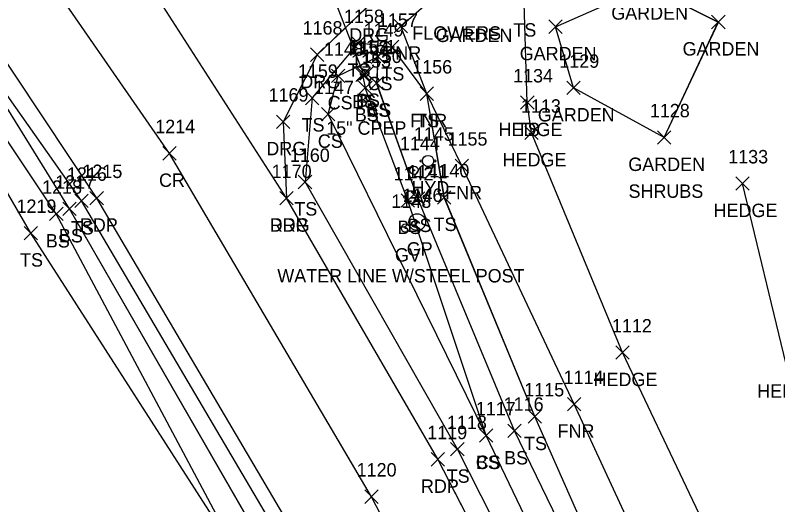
# Model space of a CAD drawing. Extents: x 1415642 to 1422021, y 544543 to 547232.
# Drawn here: x 1416447 to 1416560.6, y 546411.7 to 546484.6 of the extents above; entities that cross this region are included whole.
import ezdxf

# ---------------------------------------------------------------- set-up
doc = ezdxf.new("R2010")
doc.units = 0
for name, color, linetype in [('D_A', 7, 'Continuous'), ('D_C', 7, 'Continuous'), ('D_I', 7, 'Continuous'), ('D_TIC', 7, 'Continuous'), ('DCP', 7, 'Continuous'), ('L_A', 7, 'Continuous'), ('L_C', 7, 'Continuous'), ('L_I', 7, 'Continuous'), ('L_TIC', 7, 'Continuous'), ('LAHR', 7, 'Continuous'), ('LAPB', 7, 'Continuous'), ('LELB', 7, 'Continuous'), ('LFNC', 7, 'Continuous'), ('P_A', 7, 'Continuous'), ('P_I', 7, 'Continuous'), ('P_TIC', 7, 'Continuous'), ('PET', 7, 'Continuous'), ('PRC', 7, 'Continuous'), ('R_A', 7, 'Continuous'), ('R_C', 7, 'Continuous'), ('R_I', 7, 'Continuous'), ('R_TIC', 7, 'Continuous'), ('RDG', 7, 'Continuous'), ('RGP', 7, 'Continuous'), ('U_A', 7, 'Continuous'), ('U_I', 7, 'Continuous'), ('UWFH', 7, 'Continuous'), ('UWV', 7, 'Continuous')]:
    doc.layers.add(name, color=color, linetype=linetype)

msp = doc.modelspace()

# ---------------------------------------------------------------- linework, layer by layer
at = {"layer": 'D_TIC'}
for points in [[(1416497.95, 546474.82), (1416499.95, 546476.82)], [(1416499.95, 546474.82), (1416497.95, 546476.82)]]:
    msp.add_lwpolyline(points, dxfattribs=at)
at = {"layer": 'DCP'}
msp.add_lwpolyline([(1416498.95, 546475.82), (1416487.7, 546504.64)], dxfattribs=at)
msp.add_lwpolyline([(1416498.95, 546475.82), (1416487.7, 546504.64)], dxfattribs=at)
at = {"layer": 'L_TIC'}
for points in [[(1416503.48, 546482), (1416505.48, 546484)], [(1416505.48, 546482), (1416503.48, 546484)], [(1416526.52, 546481.92), (1416528.52, 546483.92)], [(1416528.52, 546481.92), (1416526.52, 546483.92)], [(1416550.79, 546482.62), (1416552.79, 546484.62)], [(1416552.79, 546482.62), (1416550.79, 546484.62)], [(1416550.79, 546482.62), (1416552.79, 546484.62)], [(1416552.79, 546482.62), (1416550.79, 546484.62)], [(1416497.12, 546479.46), (1416499.12, 546481.46)], [(1416499.12, 546479.46), (1416497.12, 546481.46)], [(1416502.17, 546478.89), (1416504.17, 546480.89)], [(1416504.17, 546478.89), (1416502.17, 546480.89)], [(1416500.06, 546477.45), (1416502.06, 546479.45)], [(1416502.06, 546477.45), (1416500.06, 546479.45)], [(1416498.33, 546474.96), (1416500.33, 546476.96)], [(1416500.33, 546474.96), (1416498.33, 546476.96)], [(1416494.12, 546474.6), (1416496.12, 546476.6)], [(1416496.12, 546474.6), (1416494.12, 546476.6)], [(1416497.77, 546474.76), (1416499.77, 546476.76)], [(1416499.77, 546474.76), (1416497.77, 546476.76)], [(1416498.17, 546472.82), (1416500.17, 546474.82)], [(1416500.17, 546472.82), (1416498.17, 546474.82)], [(1416498.17, 546472.82), (1416500.17, 546474.82)], [(1416500.17, 546472.82), (1416498.17, 546474.82)], [(1416499.86, 546473.51), (1416501.86, 546475.51)], [(1416501.86, 546473.51), (1416499.86, 546475.51)], [(1416499.86, 546473.51), (1416501.86, 546475.51)], [(1416501.86, 546473.51), (1416499.86, 546475.51)], [(1416529.22, 546472.8), (1416531.22, 546474.8)], [(1416531.22, 546472.8), (1416529.22, 546474.8)], [(1416507.34, 546471.94), (1416509.34, 546473.94)], [(1416509.34, 546471.94), (1416507.34, 546473.94)], [(1416507.34, 546471.94), (1416509.34, 546473.94)], [(1416509.34, 546471.94), (1416507.34, 546473.94)], [(1416490.26, 546471.3), (1416492.26, 546473.3)], [(1416492.26, 546471.3), (1416490.26, 546473.3)], [(1416522.32, 546470.61), (1416524.32, 546472.61)], [(1416524.32, 546470.61), (1416522.32, 546472.61)], [(1416522.32, 546470.61), (1416524.32, 546472.61)], [(1416524.32, 546470.61), (1416522.32, 546472.61)], [(1416492.65, 546468.87), (1416494.65, 546470.87)], [(1416494.65, 546468.87), (1416492.65, 546470.87)], [(1416522.93, 546466.1), (1416524.93, 546468.1)], [(1416524.93, 546466.1), (1416522.93, 546468.1)], [(1416542.7, 546465.42), (1416544.7, 546467.42)], [(1416544.7, 546465.42), (1416542.7, 546467.42)], [(1416542.7, 546465.42), (1416544.7, 546467.42)], [(1416544.7, 546465.42), (1416542.7, 546467.42)], [(1416512.55, 546461.2), (1416514.55, 546463.2)], [(1416514.55, 546461.2), (1416512.55, 546463.2)], [(1416489.18, 546458.78), (1416491.18, 546460.78)], [(1416491.18, 546458.78), (1416489.18, 546460.78)], [(1416489.18, 546458.78), (1416491.18, 546460.78)], [(1416491.18, 546458.78), (1416489.18, 546460.78)], [(1416554.38, 546458.55), (1416556.38, 546460.55)], [(1416556.38, 546458.55), (1416554.38, 546460.55)], [(1416455.87, 546455.96), (1416457.87, 546457.96)], [(1416457.87, 546455.96), (1416455.87, 546457.96)], [(1416504.52, 546456.03), (1416506.52, 546458.03)], [(1416506.52, 546456.03), (1416504.52, 546458.03)], [(1416506.02, 546456.32), (1416508.02, 546458.32)], [(1416508.02, 546456.32), (1416506.02, 546458.32)], [(1416509.94, 546456.47), (1416511.94, 546458.47)], [(1416511.94, 546456.47), (1416509.94, 546458.47)], [(1416454.06, 546454.78), (1416456.06, 546456.78)], [(1416456.06, 546454.78), (1416454.06, 546456.78)], [(1416452.11, 546454.02), (1416454.11, 546456.02)], [(1416454.11, 546454.02), (1416452.11, 546456.02)], [(1416448.3, 546451.17), (1416450.3, 546453.17)], [(1416450.3, 546451.17), (1416448.3, 546453.17)], [(1416536.49, 546433.36), (1416538.49, 546435.36)], [(1416538.49, 546433.36), (1416536.49, 546435.36)], [(1416529.29, 546425.68), (1416531.29, 546427.68)], [(1416531.29, 546425.68), (1416529.29, 546427.68)], [(1416523.42, 546423.83), (1416525.42, 546425.83)], [(1416525.42, 546423.83), (1416523.42, 546425.83)], [(1416520.41, 546421.69), (1416522.41, 546423.69)], [(1416522.41, 546421.69), (1416520.41, 546423.69)], [(1416516.2, 546421.01), (1416518.2, 546423.01)], [(1416518.2, 546421.01), (1416516.2, 546423.01)], [(1416516.2, 546421.01), (1416518.2, 546423.01)], [(1416518.2, 546421.01), (1416516.2, 546423.01)], [(1416511.89, 546418.96), (1416513.89, 546420.96)], [(1416513.89, 546418.96), (1416511.89, 546420.96)]]:
    msp.add_lwpolyline(points, dxfattribs=at)
at = {"layer": 'LAHR'}
for points in [[(1416601.24, 546292.69), (1416586.35, 546326.71), (1416573.12, 546362.04), (1416558.49, 546390.29), (1416537.49, 546434.36), (1416523.93, 546467.1), (1416523.32, 546471.61)], [(1416601.24, 546292.69), (1416586.35, 546326.71), (1416573.12, 546362.03), (1416558.49, 546390.29), (1416537.49, 546434.36), (1416523.93, 546467.1), (1416523.32, 546471.61)], [(1416579.62, 546377.83), (1416571.96, 546396.11), (1416561.88, 546432.63), (1416555.38, 546459.56)], [(1416579.62, 546377.83), (1416571.96, 546396.12), (1416561.88, 546432.63), (1416555.38, 546459.55)]]:
    msp.add_lwpolyline(points, dxfattribs=at)
at = {"layer": 'LAPB'}
for points in [[(1416543.7, 546466.42), (1416530.22, 546473.8), (1416527.52, 546482.92), (1416541.16, 546488.97), (1416551.79, 546483.62)], [(1416543.71, 546466.42), (1416530.22, 546473.8), (1416527.52, 546482.91), (1416541.17, 546488.97), (1416551.8, 546483.62)], [(1416543.7, 546466.42), (1416551.79, 546483.62)], [(1416543.71, 546466.42), (1416551.8, 546483.62)]]:
    msp.add_lwpolyline(points, dxfattribs=at)
at = {"layer": 'LELB'}
for points in [[(1416578, 546177.77), (1416578.55, 546199.27), (1416573.9, 546214.14), (1416552.43, 546269), (1416536.22, 546304.5), (1416520.22, 546335.71), (1416500.65, 546371.21), (1416484.25, 546405.14), (1416455.06, 546455.78), (1416435.93, 546486.65), (1416412.14, 546519.01), (1416383.64, 546557.13), (1416352.74, 546592.54), (1416331.82, 546618.14), (1416293.94, 546655.61), (1416274.22, 546680.91), (1416245.72, 546708.98), (1416224.27, 546729.93), (1416198.14, 546753.3), (1416170.94, 546765.48), (1416158.5, 546767.31), (1416141.08, 546772.75), (1416136.01, 546776.95), (1416129, 546780.64)], [(1416578, 546177.77), (1416578.55, 546199.27), (1416573.9, 546214.14), (1416552.42, 546269.01), (1416536.22, 546304.5), (1416520.22, 546335.71), (1416500.65, 546371.22), (1416484.25, 546405.15), (1416455.06, 546455.79), (1416435.93, 546486.65), (1416412.14, 546519.01), (1416383.65, 546557.13), (1416352.74, 546592.54), (1416331.82, 546618.14), (1416293.94, 546655.62), (1416274.22, 546680.91), (1416245.72, 546708.98), (1416224.27, 546729.93), (1416198.14, 546753.3), (1416170.94, 546765.48), (1416158.51, 546767.31), (1416141.09, 546772.75), (1416136.01, 546776.96), (1416129.01, 546780.64)], [(1416503.76, 546247.98), (1416498.74, 546274.69), (1416501.23, 546308.66), (1416502.98, 546324.04), (1416489.47, 546365.32), (1416480.57, 546403.46), (1416453.11, 546455.02), (1416433.2, 546484.78), (1416409.26, 546516.78), (1416378.25, 546552.92), (1416343.61, 546583.91), (1416327.57, 546614.09), (1416289.4, 546651.59), (1416267.58, 546675.69), (1416237.14, 546697.31), (1416220.66, 546725.9), (1416195.41, 546750.9), (1416170.78, 546763.33), (1416158.82, 546764.49), (1416140.16, 546770.72), (1416135.4, 546775.05), (1416128.27, 546778.63)], [(1416503.76, 546247.98), (1416498.74, 546274.69), (1416501.24, 546308.65), (1416502.98, 546324.03), (1416489.47, 546365.32), (1416480.57, 546403.46), (1416453.11, 546455.02), (1416433.2, 546484.78), (1416409.26, 546516.79), (1416378.25, 546552.92), (1416343.61, 546583.91), (1416327.58, 546614.09), (1416289.4, 546651.59), (1416267.58, 546675.69), (1416237.14, 546697.31), (1416220.66, 546725.9), (1416195.42, 546750.9), (1416170.78, 546763.33), (1416158.81, 546764.5), (1416140.16, 546770.72), (1416135.4, 546775.05), (1416128.28, 546778.62)], [(1416480.57, 546403.46), (1416449.3, 546452.17), (1416431.01, 546483.64), (1416405.55, 546512.84), (1416372.51, 546548.53), (1416341.49, 546581.99), (1416324.84, 546612.16), (1416286, 546648.13), (1416263.12, 546671.71)], [(1416480.57, 546403.46), (1416449.3, 546452.17), (1416431.01, 546483.64), (1416405.56, 546512.84), (1416372.51, 546548.53), (1416341.49, 546581.99), (1416324.84, 546612.16), (1416286, 546648.13), (1416263.12, 546671.71)], [(1416587.9, 546190.79), (1416583.62, 546199.97), (1416577.46, 546215.02), (1416552.43, 546269), (1416533.39, 546301.47), (1416525.26, 546316.84), (1416520.22, 546335.71), (1416504.13, 546372.91), (1416486.87, 546406.07), (1416456.87, 546456.96), (1416435.93, 546486.65), (1416413.88, 546519.84), (1416385.73, 546558.12)], [(1416587.91, 546190.79), (1416583.61, 546199.97), (1416577.46, 546215.02), (1416552.42, 546269.01), (1416533.39, 546301.47), (1416525.26, 546316.84), (1416520.22, 546335.71), (1416504.13, 546372.91), (1416486.87, 546406.07), (1416456.87, 546456.96), (1416435.93, 546486.65), (1416413.88, 546519.84), (1416385.73, 546558.12)], [(1416523.32, 546471.61), (1416522.83, 546486.44), (1416538.17, 546498.28)], [(1416523.32, 546471.61), (1416522.83, 546486.44), (1416538.17, 546498.28)], [(1416547.3, 546389.95), (1416538.28, 546393.51), (1416524.42, 546424.83), (1416510.94, 546457.47), (1416508.34, 546472.94), (1416503.17, 546479.89), (1416498.12, 546480.46), (1416491.26, 546472.3), (1416490.18, 546459.78)], [(1416547.3, 546389.95), (1416538.28, 546393.51), (1416524.42, 546424.83), (1416510.95, 546457.47), (1416508.35, 546472.93), (1416503.17, 546479.89), (1416498.12, 546480.46), (1416491.25, 546472.3), (1416490.18, 546459.78)], [(1416517.2, 546422.01), (1416493.65, 546469.87), (1416495.12, 546475.6), (1416501.06, 546478.45), (1416500.86, 546474.51)], [(1416517.2, 546422.02), (1416493.65, 546469.87), (1416495.12, 546475.6), (1416501.06, 546478.45), (1416500.87, 546474.51)], [(1416624.83, 546188.33), (1416609.68, 546228.85), (1416587.46, 546280.33), (1416569.58, 546317.95), (1416555.08, 546351.62), (1416539.63, 546384.17), (1416546.45, 546386.59), (1416544.38, 546389.65), (1416537.72, 546389.11), (1416521.41, 546422.69), (1416507.02, 546457.32), (1416500.86, 546474.51), (1416499.33, 546475.96), (1416498.77, 546475.76), (1416499.17, 546473.82)], [(1416624.83, 546188.34), (1416609.68, 546228.85), (1416587.45, 546280.34), (1416569.58, 546317.95), (1416555.08, 546351.63), (1416539.63, 546384.17), (1416546.45, 546386.59), (1416544.38, 546389.64), (1416537.72, 546389.12), (1416521.42, 546422.68), (1416507.02, 546457.32), (1416500.87, 546474.51), (1416499.33, 546475.96), (1416498.77, 546475.76), (1416499.17, 546473.83)], [(1416624.13, 546188.48), (1416606.9, 546227.58), (1416585.22, 546279.32), (1416567.76, 546317.19), (1416553.66, 546350.45), (1416534.43, 546386.06), (1416517.2, 546422.02), (1416505.52, 546457.03), (1416499.17, 546473.83)], [(1416624.13, 546188.48), (1416606.9, 546227.58), (1416585.22, 546279.32), (1416567.76, 546317.19), (1416553.66, 546350.45), (1416534.43, 546386.06), (1416517.2, 546422.01), (1416505.52, 546457.03), (1416499.17, 546473.82)], [(1416620.93, 546187.09), (1416604.47, 546226.81), (1416580.95, 546278.02), (1416564.18, 546315.62), (1416549.05, 546348.52), (1416530.53, 546385.22), (1416512.89, 546419.96), (1416490.18, 546459.78)], [(1416620.93, 546187.09), (1416604.48, 546226.8), (1416580.95, 546278.02), (1416564.18, 546315.62), (1416549.05, 546348.51), (1416530.53, 546385.22), (1416512.89, 546419.96), (1416490.18, 546459.78)]]:
    msp.add_lwpolyline(points, dxfattribs=at)
at = {"layer": 'LFNC'}
for points in [[(1416616.17, 546291.53), (1416602.64, 546290.41), (1416594.37, 546289.3), (1416578.97, 546322.54), (1416563.77, 546356.27), (1416548.95, 546386.35), (1416547.3, 546389.95), (1416530.29, 546426.68), (1416513.55, 546462.2), (1416508.34, 546472.94), (1416504.48, 546483), (1416512.48, 546489.98)], [(1416616.17, 546291.53), (1416602.64, 546290.41), (1416594.37, 546289.3), (1416578.97, 546322.54), (1416563.77, 546356.27), (1416548.95, 546386.35), (1416547.3, 546389.95), (1416530.29, 546426.68), (1416513.55, 546462.2), (1416508.35, 546472.93), (1416504.48, 546483), (1416512.48, 546489.98)]]:
    msp.add_lwpolyline(points, dxfattribs=at)
at = {"layer": 'P_TIC'}
for points in [[(1416468.99, 546463.05), (1416470.99, 546465.05)], [(1416470.99, 546463.05), (1416468.99, 546465.05)], [(1416458.13, 546456.37), (1416460.13, 546458.37)], [(1416460.13, 546456.37), (1416458.13, 546458.37)], [(1416486.43, 546456.37), (1416488.43, 546458.37)], [(1416488.43, 546456.37), (1416486.43, 546458.37)], [(1416508.97, 546417.46), (1416510.97, 546419.46)], [(1416510.97, 546417.46), (1416508.97, 546419.46)], [(1416499.09, 546411.89), (1416501.09, 546413.89)], [(1416501.09, 546411.89), (1416499.09, 546413.89)]]:
    msp.add_lwpolyline(points, dxfattribs=at)
at = {"layer": 'PET'}
for points in [[(1416619.56, 546186.67), (1416601.63, 546226.16), (1416579.47, 546277.45), (1416562.03, 546315.23), (1416547.08, 546347.32), (1416527.73, 546384.04), (1416509.97, 546418.47), (1416487.43, 546457.37), (1416462.82, 546495.68), (1416435.56, 546537.44), (1416408.53, 546574.62)], [(1416619.56, 546186.67), (1416601.62, 546226.16), (1416579.47, 546277.45), (1416562.03, 546315.23), (1416547.08, 546347.32), (1416527.73, 546384.03), (1416509.97, 546418.46), (1416487.43, 546457.37), (1416462.82, 546495.68), (1416435.56, 546537.44), (1416408.53, 546574.61)], [(1416599.36, 546175.05), (1416589.42, 546196.6), (1416580.61, 546216.08), (1416556.35, 546269.48), (1416540.49, 546305), (1416525.46, 546337.37), (1416506.55, 546374.02), (1416489.16, 546406.45), (1416459.13, 546457.37), (1416438.7, 546488.16), (1416417.68, 546520.98), (1416388.9, 546560.28)], [(1416599.36, 546175.05), (1416589.42, 546196.6), (1416580.62, 546216.08), (1416556.34, 546269.48), (1416540.49, 546305), (1416525.46, 546337.38), (1416506.55, 546374.02), (1416489.16, 546406.45), (1416459.13, 546457.38), (1416438.7, 546488.17), (1416417.68, 546520.98), (1416388.9, 546560.28)]]:
    msp.add_lwpolyline(points, dxfattribs=at)
at = {"layer": 'PRC'}
for points in [[(1416610.25, 546183.67), (1416586.12, 546227.19), (1416567.64, 546274.51), (1416551.19, 546309.95), (1416536.28, 546342.88), (1416517.21, 546379.83), (1416500.09, 546412.89), (1416469.99, 546464.05), (1416448.59, 546494.95), (1416427.64, 546528.31), (1416425.29, 546532.23), (1416399.16, 546568.17)], [(1416610.26, 546183.67), (1416586.11, 546227.19), (1416567.64, 546274.51), (1416551.18, 546309.96), (1416536.27, 546342.88), (1416517.21, 546379.83), (1416500.09, 546412.89), (1416469.99, 546464.05), (1416448.59, 546494.95), (1416427.64, 546528.31), (1416425.29, 546532.24), (1416399.16, 546568.17)]]:
    msp.add_lwpolyline(points, dxfattribs=at)
at = {"layer": 'R_TIC'}
for points in [[(1416490.99, 546477.75), (1416492.99, 546479.75)], [(1416492.99, 546477.75), (1416490.99, 546479.75)], [(1416485.93, 546467.76), (1416487.93, 546469.76)], [(1416487.93, 546467.76), (1416485.93, 546469.76)], [(1416486.43, 546456.37), (1416488.43, 546458.37)], [(1416488.43, 546456.37), (1416486.43, 546458.37)]]:
    msp.add_lwpolyline(points, dxfattribs=at)
at = {"layer": 'RDG'}
for points in [[(1416534.66, 546503.43), (1416512.03, 546493.22), (1416510.86, 546493.07), (1416499.29, 546485.7), (1416491.99, 546478.75), (1416486.93, 546468.76), (1416487.43, 546457.37)], [(1416534.66, 546503.43), (1416512.03, 546493.22), (1416510.86, 546493.07), (1416499.29, 546485.71), (1416491.99, 546478.75), (1416486.93, 546468.76), (1416487.43, 546457.37)]]:
    msp.add_lwpolyline(points, dxfattribs=at)
at = {"layer": 'RGP'}
msp.add_line((1416506.91, 546453.81), (1416506.91, 546453.81), dxfattribs=at)
for radius in [1.25, 0.0833]:
    msp.add_circle((1416506.91, 546453.81), radius, dxfattribs=at)
at = {"layer": 'UWFH'}
msp.add_line((1416508.53, 546462.92), (1416508.53, 546462.92), dxfattribs=at)
for centre, radius in [((1416508.53, 546462.92), 0.833), ((1416507.53, 546462.92), 0.167), ((1416509.53, 546462.92), 0.167), ((1416508.53, 546461.92), 0.167)]:
    msp.add_circle(centre, radius, dxfattribs=at)
at = {"layer": 'UWV'}
for centre, radius in [((1416506.44, 546461.52), 0.625), ((1416506.44, 546461.52), 0.0833), ((1416505.17, 546452.92), 0.625), ((1416505.17, 546452.92), 0.0833)]:
    msp.add_circle(centre, radius, dxfattribs=at)

# ---------------------------------------------------------------- texts
at = {"layer": 'D_A'}
msp.add_text('P', height=2, dxfattribs=at).set_placement((1416498.33, 546470.82))
at = {"layer": 'D_C'}
msp.add_text('15" CPEP', height=2, dxfattribs=at).set_placement((1416493.34, 546466.82))
at = {"layer": 'D_I'}
msp.add_text('1154', height=2, dxfattribs=at).set_placement((1416496.83, 546478.82))
at = {"layer": 'L_A'}
for s, p in [('GARDEN', (1416535.83, 546483.97)), ('GARDEN', (1416509.65, 546480.63)), ('GARDEN', (1416509.65, 546480.63)), ('TS', (1416521.24, 546481.44)), ('GARDEN', (1416546.46, 546478.62)), ('GARDEN', (1416546.46, 546478.62)), ('FNR', (1416502.01, 546478)), ('GARDEN', (1416522.19, 546477.92)), ('TS', (1416496.53, 546475.46)), ('TS', (1416501.57, 546474.89)), ('CS', (1416499.5, 546473.45)), ('CS', (1416493.56, 546470.6)), ('BS', (1416497.21, 546470.76)), ('BS', (1416497.77, 546470.96)), ('CS', (1416499.31, 546469.51)), ('BS', (1416499.31, 546469.51)), ('BS', (1416497.61, 546468.82)), ('BS', (1416497.61, 546468.82)), ('GARDEN', (1416524.89, 546468.8)), ('TS', (1416489.67, 546467.3)), ('FNR', (1416505.88, 546467.94)), ('TS', (1416506.75, 546467.94)), ('HEDGE', (1416519.03, 546466.61)), ('TS', (1416521.73, 546466.61)), ('CS', (1416492.09, 546464.87)), ('HEDGE', (1416519.63, 546462.1)), ('GARDEN', (1416538.37, 546461.42)), ('GARDEN', (1416538.37, 546461.42)), ('FNR', (1416511.08, 546457.2)), ('TS', (1416488.59, 546454.78)), ('TS', (1416488.59, 546454.78)), ('HEDGE', (1416551.09, 546454.55)), ('BS', (1416505.46, 546452.32)), ('TS', (1416509.35, 546452.47)), ('TS', (1416455.28, 546451.96)), ('BS', (1416503.96, 546452.03)), ('BS', (1416451.55, 546450.02)), ('BS', (1416453.5, 546450.78)), ('TS', (1416447.71, 546447.17)), ('HEDGE', (1416533.19, 546429.36)), ('HEDGE', (1416557.58, 546427.63)), ('FNR', (1416527.83, 546421.68)), ('TS', (1416522.83, 546419.83)), ('CS', (1416515.64, 546417.01)), ('BS', (1416515.64, 546417.01)), ('BS', (1416519.86, 546417.69)), ('TS', (1416511.3, 546414.96))]:
    msp.add_text(s, height=2, dxfattribs=at).set_placement(p)
at = {"layer": 'L_C'}
for s, p in [('FLOWERS', (1416506.18, 546480.98)), ('SHRUBS', (1416538.4, 546457.42)), ('SHRUBS', (1416538.4, 546457.42))]:
    msp.add_text(s, height=2, dxfattribs=at).set_placement(p)
at = {"layer": 'L_I'}
for s, p in [('1158', (1416495.99, 546483.46)), ('1157', (1416501.04, 546482.89)), ('1149', (1416498.93, 546481.45)), ('1148', (1416493, 546478.6)), ('1152', (1416496.64, 546478.76)), ('1151', (1416497.77, 546478.96)), ('1150', (1416498.65, 546477.51)), ('1150', (1416498.65, 546477.51)), ('1153', (1416497.05, 546476.82)), ('1153', (1416497.05, 546476.82)), ('1129', (1416528.09, 546476.8)), ('1159', (1416489.12, 546475.3)), ('1156', (1416506.16, 546475.94)), ('1156', (1416506.16, 546475.94)), ('1134', (1416521.2, 546474.61)), ('1134', (1416521.2, 546474.61)), ('1147', (1416491.53, 546472.87)), ('1113', (1416522.37, 546470.1)), ('1128', (1416541.58, 546469.42)), ('1128', (1416541.58, 546469.42)), ('1155', (1416511.42, 546465.2)), ('1160', (1416487.92, 546462.78)), ('1160', (1416487.92, 546462.78)), ('1133', (1416553.26, 546462.55)), ('1141', (1416505.46, 546460.32)), ('1140', (1416508.73, 546460.47)), ('1216', (1416454.69, 546459.96)), ('1142', (1416503.39, 546460.03)), ('1218', (1416450.99, 546458.02)), ('1217', (1416452.94, 546458.78)), ('1219', (1416447.17, 546455.17)), ('1112', (1416535.93, 546437.36)), ('1114', (1416528.73, 546429.68)), ('1115', (1416522.86, 546427.83)), ('1117', (1416515.64, 546425.01)), ('1117', (1416515.64, 546425.01)), ('1116', (1416519.8, 546425.69)), ('1118', (1416511.34, 546422.96))]:
    msp.add_text(s, height=2, dxfattribs=at).set_placement(p)
at = {"layer": 'P_A'}
for s, p in [('CR', (1416468.42, 546459.05)), ('RDP', (1416456.62, 546452.37)), ('RDP', (1416484.92, 546452.37)), ('RDP', (1416507.46, 546413.46))]:
    msp.add_text(s, height=2, dxfattribs=at).set_placement(p)
at = {"layer": 'P_I'}
for s, p in [('1214', (1416467.86, 546467.05)), ('1215', (1416457, 546460.37)), ('1170', (1416485.22, 546460.37)), ('1119', (1416508.4, 546421.46)), ('1120', (1416497.88, 546415.89))]:
    msp.add_text(s, height=2, dxfattribs=at).set_placement(p)
at = {"layer": 'R_A'}
for s, p in [('DRG', (1416496.78, 546480.7)), ('DRG', (1416489.48, 546473.75)), ('DRG', (1416484.42, 546463.76)), ('DRG', (1416484.92, 546452.37)), ('GP', (1416505.34, 546448.81))]:
    msp.add_text(s, height=2, dxfattribs=at).set_placement(p)
at = {"layer": 'R_C'}
msp.add_text('WATER LINE W/STEEL POST', height=2, dxfattribs=at).set_placement((1416486.05, 546444.81))
at = {"layer": 'R_I'}
for s, p in [('1168', (1416489.82, 546481.75)), ('1169', (1416484.75, 546471.76)), ('1170', (1416485.22, 546460.37)), ('1146', (1416504.72, 546456.81))]:
    msp.add_text(s, height=2, dxfattribs=at).set_placement(p)
at = {"layer": 'U_A'}
for s, p in [('HYD', (1416506.05, 546457.92)), ('GV', (1416504.85, 546456.52)), ('GV', (1416503.58, 546447.92))]:
    msp.add_text(s, height=2, dxfattribs=at).set_placement(p)
at = {"layer": 'U_I'}
for s, p in [('1145', (1416506.4, 546465.92)), ('1144', (1416504.32, 546464.52)), ('1143', (1416503.05, 546455.92))]:
    msp.add_text(s, height=2, dxfattribs=at).set_placement(p)

doc.saveas('drawing.dxf')
